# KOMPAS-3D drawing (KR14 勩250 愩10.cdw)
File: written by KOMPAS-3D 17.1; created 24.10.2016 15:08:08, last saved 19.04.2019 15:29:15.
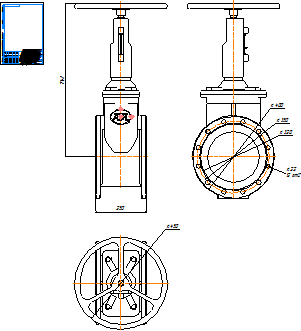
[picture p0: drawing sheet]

Sheet 1: A4, portrait

Title block, sheet 1: name: KR14 Ду250 Ру10; material: Внимание! Данный продукт является объектом авторского права ООО «Торговый Дом АДЛ». / Запрещается изменение, копирование, распространение / (в том числе путем копирования на другие сайты и ресурсы в Интернете) / или любое иное использование информации и объектов без предварительного / согласия правообладателя (ООО «Торговый Дом АДЛ»).; mass: 201; sheets: 1; organisation: ООО "Торговый дом АДЛ"; sheet format: A4; stored path: \\adlc.lan\data\АДЛ_ПКД\3D-модели\ADL production\Клиновые задвижки серии KR ГРАНАР\Клиновые задвижки KR14\kompas 2d\KR14 Ду250 Ру10.cdw

Views: Вид 1, Проекционный вид 3
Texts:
  Klimkovich
  ADL
Dimensions and other numbers on the sheet: 250; 742; 450; 1:1; 1; 201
